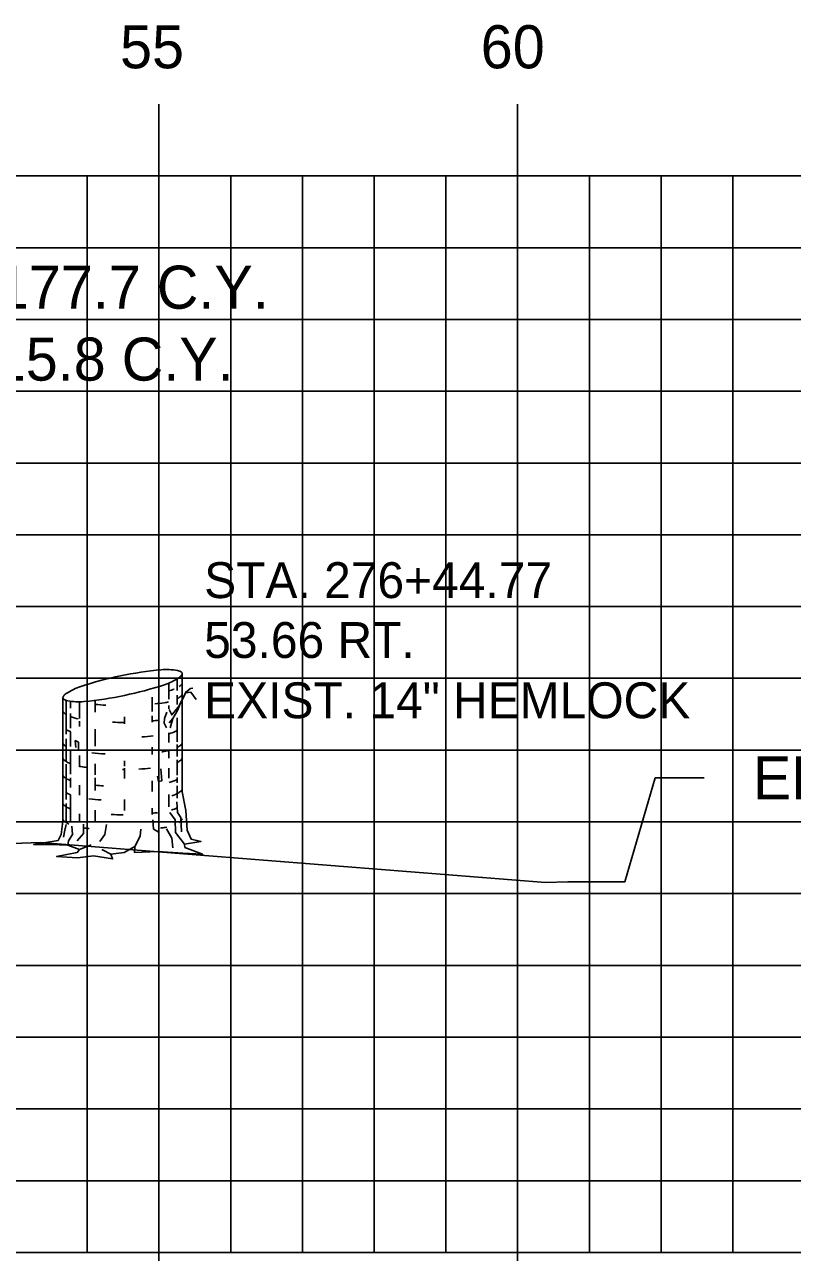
# Model space of a CAD drawing. Extents: x 854008 to 854178, y 366268 to 366378.
# Drawn here: x 854144.23 to 854154.93, y 366277.24 to 366294.35 of the extents above; entities that cross this region are included whole.
import ezdxf

# ---------------------------------------------------------------- set-up
doc = ezdxf.new("R2010")
doc.units = 0
for name, color, linetype in [('ANNOTATION', 7, 'Continuous'), ('D_Text_Monospaced', 7, 'Continuous'), ('D_Text_Standard', 7, 'Continuous'), ('H_V ANNOTATION', 7, 'Continuous'), ('MAJOR', 7, 'Continuous'), ('MINOR', 7, 'Continuous'), ('S_Roadway_Centerline', 7, 'Continuous'), ('S_Trees_Conifer_Pay', 7, 'Continuous')]:
    doc.layers.add(name, color=color, linetype=linetype)

msp = doc.modelspace()

# ---------------------------------------------------------------- linework, layer by layer
at = {"layer": 'D_Text_Standard'}
msp.add_lwpolyline([(854152.599, 366282.401), (854153.023, 366283.848), (854153.703, 366283.848)], dxfattribs=at)
at = {"layer": 'MAJOR'}
for p, q in [((854146.103, 366293.238), (854146.103, 366292.236)), ((854151.103, 366293.238), (854151.103, 366292.236)), ((854021.103, 366292.236), (854161.103, 366292.236)), ((854021.103, 366292.236), (854161.103, 366292.236)), ((854146.103, 366277.236), (854146.103, 366292.236)), ((854151.103, 366277.236), (854151.103, 366292.236)), ((854021.103, 366287.236), (854161.103, 366287.236)), ((854021.103, 366282.236), (854161.103, 366282.236)), ((854021.103, 366277.236), (854161.103, 366277.236)), ((854021.103, 366277.236), (854161.103, 366277.236)), ((854146.103, 366276.234), (854146.103, 366277.236)), ((854151.103, 366276.234), (854151.103, 366277.236))]:
    msp.add_line(p, q, dxfattribs=at)
at = {"layer": 'MINOR'}
for p, q in [((854145.103, 366277.236), (854145.103, 366292.236)), ((854147.103, 366277.236), (854147.103, 366292.236)), ((854148.103, 366277.236), (854148.103, 366292.236)), ((854149.103, 366277.236), (854149.103, 366292.236)), ((854150.103, 366277.236), (854150.103, 366292.236)), ((854152.103, 366277.236), (854152.103, 366292.236)), ((854153.103, 366277.236), (854153.103, 366292.236)), ((854154.103, 366277.236), (854154.103, 366292.236)), ((854021.103, 366291.236), (854161.103, 366291.236)), ((854021.103, 366290.236), (854161.103, 366290.236)), ((854021.103, 366289.236), (854161.103, 366289.236)), ((854021.103, 366288.236), (854161.103, 366288.236)), ((854021.103, 366286.236), (854161.103, 366286.236)), ((854021.103, 366285.236), (854161.103, 366285.236)), ((854021.103, 366284.236), (854161.103, 366284.236)), ((854021.103, 366283.236), (854161.103, 366283.236)), ((854021.103, 366281.236), (854161.103, 366281.236)), ((854021.103, 366280.236), (854161.103, 366280.236)), ((854021.103, 366279.236), (854161.103, 366279.236)), ((854021.103, 366278.236), (854161.103, 366278.236))]:
    msp.add_line(p, q, dxfattribs=at)
at = {"layer": 'S_Roadway_Centerline'}
msp.add_lwpolyline([(854119.24, 366283.569), (854127.488, 366282.734), (854134.932, 366282.61), (854144.452, 366282.95), (854151.493, 366282.391), (854151.803, 366282.4), (854152.599, 366282.401)], dxfattribs=at)
at = {"layer": 'S_Trees_Conifer_Pay'}
for p, q in [((854146.356, 366285.23), (854146.356, 366285.067)), ((854146.427, 366283.655), (854146.427, 366285.302)), ((854146.238, 366285.169), (854146.238, 366284.946)), ((854144.763, 366283.245), (854144.763, 366284.967)), ((854144.81, 366284.929), (854144.81, 366284.458)), ((854144.869, 366284.918), (854144.869, 366284.82)), ((854144.994, 366284.91), (854144.994, 366284.678)), ((854145.214, 366284.931), (854145.214, 366284.763)), ((854146.01, 366284.973), (854146.01, 366284.773)), ((854146.356, 366284.999), (854146.356, 366284.871)), ((854144.869, 366284.746), (854144.869, 366284.542)), ((854146.01, 366284.715), (854146.01, 366284.627)), ((854146.238, 366284.857), (854146.238, 366284.81)), ((854144.994, 366284.637), (854144.994, 366284.563)), ((854145.62, 366284.699), (854145.62, 366284.604)), ((854146.295, 366284.674), (854146.244, 366284.614)), ((854146.356, 366284.684), (854146.356, 366284.349)), ((854144.81, 366284.394), (854144.81, 366284.085)), ((854144.869, 366284.484), (854144.869, 366284.285)), ((854145.214, 366284.526), (854145.214, 366284.289)), ((854146.238, 366284.475), (854146.238, 366284.343)), ((854144.869, 366284.238), (854144.869, 366283.902)), ((854146.01, 366284.279), (854146.01, 366284.174)), ((854146.238, 366284.232), (854146.238, 366284.122)), ((854146.356, 366284.312), (854146.356, 366284.149)), ((854144.81, 366284.038), (854144.81, 366283.546)), ((854144.994, 366284.16), (854144.994, 366284.021)), ((854145.214, 366284.044), (854145.214, 366283.892)), ((854145.62, 366284.085), (854145.62, 366284.011)), ((854146.356, 366284.102), (854146.356, 366283.885)), ((854144.869, 366283.849), (854144.869, 366283.713)), ((854145.214, 366283.849), (854145.214, 366283.675)), ((854145.62, 366283.986), (854145.62, 366283.838)), ((854146.238, 366283.986), (854146.238, 366283.845)), ((854146.356, 366283.854), (854146.356, 366283.78)), ((854144.994, 366283.749), (854144.994, 366283.608)), ((854146.01, 366283.807), (854146.01, 366283.661)), ((854146.356, 366283.74), (854146.356, 366283.566)), ((854144.869, 366283.614), (854144.869, 366283.235)), ((854145.62, 366283.546), (854145.62, 366283.393)), ((854146.238, 366283.618), (854146.238, 366283.445)), ((854144.81, 366283.492), (854144.81, 366283.245)), ((854144.994, 366283.346), (854144.994, 366283.251)), ((854145.214, 366283.398), (854145.214, 366283.245)), ((854146.01, 366283.429), (854146.01, 366283.34)), ((854144.994, 366282.852), (854145.157, 366282.915)), ((854145.431, 366282.788), (854145.305, 366282.852))]:
    msp.add_line(p, q, dxfattribs=at)
for points in [[(854146.244, 366284.8), (854146.281, 366284.726), (854146.328, 366284.783), (854146.386, 366284.851), (854146.478, 366285.045), (854146.543, 366285.092), (854146.574, 366285.099)], [(854146.259, 366284.547), (854146.295, 366284.674), (854146.359, 366284.789), (854146.39, 366284.857), (854146.459, 366285.003)], [(854146.473, 366285.033), (854146.549, 366285.041), (854146.621, 366284.942)], [(854146.211, 366284.763), (854146.18, 366284.678), (854146.176, 366284.61), (854146.207, 366284.547)], [(854144.942, 366284.272), (854144.936, 366284.368), (854144.98, 366284.345), (854144.98, 366284.25)], [(854146.081, 366283.873), (854146.094, 366283.797), (854146.141, 366283.807), (854146.129, 366283.974)], [(854146.427, 366283.655), (854146.478, 366283.393), (854146.495, 366283.12), (854146.553, 366282.994), (854146.688, 366282.963), (854146.458, 366282.926), (854146.458, 366282.926), (854146.464, 366282.879), (854146.711, 366282.784), (854146.437, 366282.801), (854146.081, 366282.821), (854145.76, 366282.81), (854145.767, 366282.893), (854145.618, 366282.81), (854145.431, 366282.788), (854145.455, 366282.72), (854145.188, 366282.763), (854144.967, 366282.736), (854144.675, 366282.753), (854144.963, 366282.81), (854144.994, 366282.852), (854144.831, 366282.91), (854144.595, 366282.92), (854144.354, 366282.92), (854144.696, 366282.978), (854144.737, 366283.058), (854144.763, 366283.245)], [(854146.353, 366283.513), (854146.359, 366283.367), (854146.406, 366283.299), (854146.417, 366283.099)], [(854146.254, 366283.367), (854146.328, 366283.262), (854146.333, 366283.089), (854146.458, 366282.926)], [(854144.811, 366283.198), (854144.79, 366283.12), (854144.77, 366283.025)], [(854144.889, 366283.177), (854144.895, 366283.062), (854144.842, 366282.973), (854144.831, 366282.91)], [(854145.052, 366283.204), (854145.052, 366283.072), (854144.963, 366282.973)], [(854145.278, 366282.963), (854145.346, 366283.058), (854145.373, 366283.198)], [(854146.017, 366283.262), (854146.028, 366283.136), (854146.102, 366283.093)], [(854145.767, 366282.893), (854145.841, 366283.035), (854145.85, 366283.136)], [(854146.295, 366282.873), (854146.281, 366283.011), (854146.207, 366283.14)]]:
    msp.add_lwpolyline(points, dxfattribs=at)
for centre, radius, start, end in [((854146.619, 366280.199), 5.179, 101.7194, 108.0594), ((854146.619, 366280.199), 5.179, 95.3794, 101.7194), ((854146.209, 366284.557), 0.802, 79.2194, 95.3794), ((854145.929, 366285.908), 0.802, 288.0594, 304.2194), ((854146.312, 366285.098), 0.251, 71.0501, 79.2194), ((854146.238, 366285.452), 0.251, 304.2194, 312.3887), ((854146.367, 366285.258), 0.0817, 56.7194, 71.0501), ((854146.352, 366285.327), 0.0817, 312.3887, 326.7194), ((854146.383, 366285.282), 0.0527, 46.923, 56.7194), ((854146.397, 366285.298), 0.0314, 34.2194, 46.923), ((854146.376, 366285.312), 0.0527, 326.7194, 336.5158), ((854146.401, 366285.301), 0.0264, 23.4074, 34.2194), ((854146.405, 366285.302), 0.0226, 11.7194, 23.4074), ((854146.396, 366285.303), 0.0314, 336.5158, 349.2194), ((854146.405, 366285.302), 0.0226, 0.0315, 11.7194), ((854146.401, 366285.302), 0.0264, 349.2194, 0.0315), ((854145.262, 366284.361), 0.802, 108.0594, 124.2194), ((854144.572, 366290.069), 5.179, 281.7194, 288.0594), ((854146.096, 366285.615), 0.571, 284.4317, 292.4132), ((854146.296, 366285.27), 0.172, 300, 311.2506), ((854146.368, 366285.188), 0.0624, 311.2506, 330), ((854146.384, 366285.179), 0.0441, 330, 343.9485), ((854146.394, 366285.176), 0.0334, 343.9485, 354.2151), ((854144.79, 366284.966), 0.0264, 169.2194, 180.0315), ((854144.786, 366284.966), 0.0226, 180.0315, 191.7194), ((854144.795, 366284.965), 0.0314, 156.5158, 169.2194), ((854144.786, 366284.966), 0.0226, 191.7194, 203.4074), ((854144.789, 366284.968), 0.0264, 203.4074, 214.2194), ((854144.814, 366284.957), 0.0527, 146.7194, 156.5158), ((854144.794, 366284.971), 0.0314, 214.2194, 226.923), ((854144.838, 366284.941), 0.0817, 132.3887, 146.7194), ((854144.808, 366284.986), 0.0527, 226.923, 236.7194), ((854144.824, 366285.01), 0.0817, 236.7194, 251.0501), ((854144.952, 366284.816), 0.251, 124.2194, 132.3887), ((854144.879, 366285.17), 0.251, 251.0501, 259.2194), ((854144.982, 366285.711), 0.802, 259.2194, 275.3794), ((854144.572, 366290.069), 5.179, 275.3794, 281.7194), ((854145.596, 366288.979), 4.124, 264.6955, 266.7331), ((854145.596, 366288.979), 4.124, 276.238, 278.1032), ((854146.096, 366285.461), 0.571, 278.1032, 284.3667), ((854146.096, 366285.461), 0.571, 297.0237, 300), ((854146.296, 366285.116), 0.172, 300, 311.2506), ((854146.368, 366285.033), 0.0624, 311.2506, 330), ((854146.384, 366285.024), 0.0441, 330, 343.9485), ((854146.394, 366285.021), 0.0334, 343.9485, 354.2151), ((854144.795, 366284.788), 0.0334, 163.9485, 180), ((854144.795, 366284.788), 0.0334, 180, 196.0515), ((854144.806, 366284.791), 0.0441, 196.0515, 210), ((854144.822, 366284.8), 0.0624, 210, 228.7494), ((854144.894, 366284.883), 0.172, 228.7494, 240), ((854145.093, 366285.228), 0.571, 240, 240.3367), ((854145.093, 366285.228), 0.571, 246.8597, 257.9846), ((854145.594, 366288.746), 4.124, 268.0751, 270), ((854145.594, 366288.746), 4.124, 270, 270.3581), ((854145.594, 366288.746), 4.124, 275.7849, 277.0558), ((854146.394, 366284.577), 0.0334, 343.9485, 354.2151), ((854145.095, 366285.017), 0.571, 240, 247.0587), ((854145.595, 366288.535), 4.124, 273.7052, 275.9504), ((854146.096, 366285.017), 0.571, 284.4493, 297.0429), ((854144.795, 366284.342), 0.0334, 163.9485, 180), ((854144.795, 366284.342), 0.0334, 180, 196.0515), ((854144.806, 366284.345), 0.0441, 196.0515, 210), ((854144.822, 366284.354), 0.0624, 210, 228.7494), ((854144.894, 366284.436), 0.172, 228.7494, 240), ((854145.093, 366284.781), 0.571, 240, 240.3367), ((854145.594, 366288.299), 4.124, 264.081, 266.6676), ((854145.594, 366288.299), 4.124, 277.6125, 278.1032), ((854146.095, 366284.781), 0.571, 278.1032, 286.9296), ((854146.095, 366284.781), 0.571, 297.1896, 300), ((854146.294, 366284.436), 0.172, 300, 311.2506), ((854146.367, 366284.354), 0.0624, 311.2506, 330), ((854146.382, 366284.345), 0.0441, 330, 343.9485), ((854146.393, 366284.342), 0.0334, 343.9485, 354.2151), ((854144.795, 366284.132), 0.0334, 163.9485, 180), ((854144.795, 366284.132), 0.0334, 180, 196.0515), ((854144.806, 366284.135), 0.0441, 196.0515, 210), ((854144.822, 366284.144), 0.0624, 210, 228.7494), ((854144.894, 366284.226), 0.172, 228.7494, 240), ((854145.093, 366284.571), 0.571, 240, 246.8597), ((854146.095, 366284.571), 0.571, 297.1896, 300), ((854146.294, 366284.226), 0.172, 300, 311.2506), ((854146.367, 366284.144), 0.0624, 311.2506, 330), ((854146.382, 366284.135), 0.0441, 330, 343.9485), ((854146.393, 366284.132), 0.0334, 343.9485, 354.2151), ((854144.795, 366283.895), 0.0334, 163.9485, 180), ((854144.795, 366283.895), 0.0334, 180, 196.0515), ((854144.806, 366283.898), 0.0441, 196.0515, 210), ((854144.822, 366283.907), 0.0624, 210, 228.7494), ((854144.894, 366283.99), 0.172, 228.7494, 240), ((854145.093, 366284.571), 0.571, 259.2707, 261.8968), ((854145.594, 366288.089), 4.124, 261.8968, 263.1474), ((854145.594, 366288.089), 4.124, 270, 270.3581), ((854145.594, 366288.089), 4.124, 273.1493, 275.4569), ((854144.795, 366283.697), 0.0334, 163.9485, 180), ((854145.093, 366284.335), 0.571, 240, 246.8597), ((854145.594, 366287.852), 4.124, 264.716, 266.3193), ((854146.095, 366284.335), 0.571, 285.3983, 297.1896), ((854146.367, 366283.709), 0.0624, 311.2506, 330), ((854146.382, 366283.7), 0.0441, 330, 343.9485), ((854146.393, 366283.697), 0.0334, 343.9485, 354.2151), ((854144.795, 366283.502), 0.0334, 163.9485, 180), ((854145.082, 366284.143), 0.571, 241.2369, 248.0268), ((854145.594, 366287.654), 4.124, 263.4991, 265.8397), ((854146.095, 366284.137), 0.571, 289.2907, 300), ((854146.294, 366283.792), 0.172, 300, 311.2506), ((854144.795, 366283.502), 0.0334, 180, 196.0515), ((854144.806, 366283.504), 0.0441, 196.0515, 210), ((854144.822, 366283.514), 0.0624, 210, 228.7494), ((854144.894, 366283.596), 0.172, 228.7494, 240), ((854145.093, 366283.941), 0.571, 240, 246.8597), ((854145.594, 366287.459), 4.124, 267.8117, 270), ((854145.594, 366287.459), 4.124, 270, 270.1328), ((854145.594, 366287.459), 4.124, 275.7849, 276.7896), ((854146.095, 366283.941), 0.571, 288.5067, 297.2721), ((854144.795, 366283.281), 0.0334, 163.9485, 180), ((854144.795, 366283.281), 0.0334, 180, 196.0515), ((854144.806, 366283.284), 0.0441, 196.0515, 210), ((854144.822, 366283.293), 0.0624, 210, 228.7494), ((854144.894, 366283.376), 0.172, 228.7494, 240), ((854145.093, 366283.721), 0.571, 240, 244.5314), ((854146.095, 366283.721), 0.571, 278.1032, 281.637), ((854146.294, 366283.376), 0.172, 300, 311.2506), ((854146.367, 366283.293), 0.0624, 311.2506, 330), ((854146.382, 366283.284), 0.0441, 330, 343.9485), ((854146.393, 366283.281), 0.0334, 343.9485, 354.2151), ((854145.594, 366287.239), 4.124, 262.4438, 263.512), ((854145.594, 366287.239), 4.124, 277.3684, 278.1032)]:
    msp.add_arc(centre, radius, start, end, dxfattribs=at)

# ---------------------------------------------------------------- texts
at = {"layer": 'ANNOTATION'}
for s, p in [('CUT = 177.7 C.Y.', (854141.279, 366290.386)), ('FILL = 15.8 C.Y.', (854141.279, 366289.384))]:
    msp.add_text(s, height=0.6, dxfattribs=at).set_placement(p)
at = {"layer": 'D_Text_Monospaced'}
for s, height, p in [('STA. 276+44.77', 0.49998, (854146.733, 366286.354)), ('53.66 RT.', 0.5, (854146.733, 366285.52)), ('EXIST. 14" HEMLOCK', 0.49998, (854146.733, 366284.68))]:
    msp.add_text(s, height=height, dxfattribs=at).set_placement(p)
at = {"layer": 'D_Text_Standard'}
msp.add_text('ELEV. = 275.16', height=0.6, dxfattribs=at).set_placement((854154.383, 366283.548))
at = {"layer": 'H_V ANNOTATION'}
for s, p in [('55', (854145.56, 366293.736)), ('60', (854150.589, 366293.736))]:
    msp.add_text(s, height=0.6, dxfattribs=at).set_placement(p)

doc.saveas('drawing.dxf')
